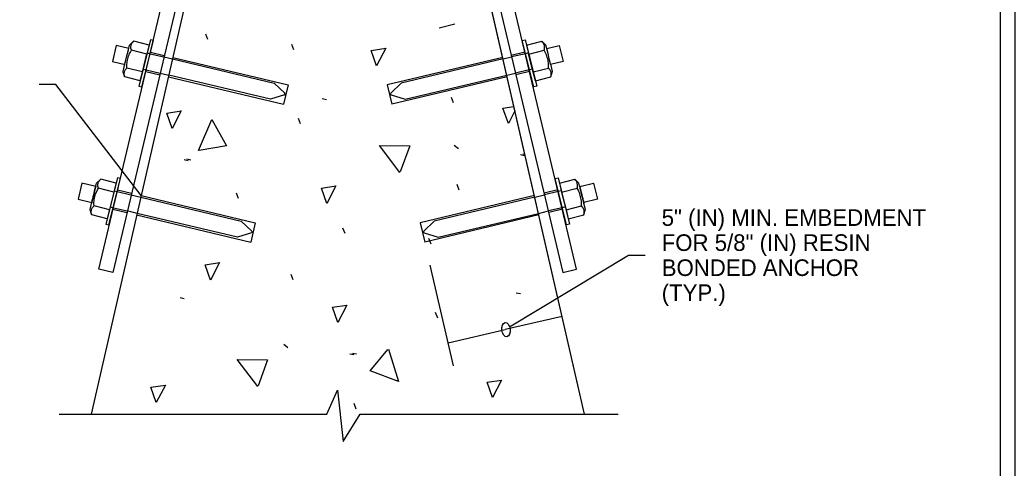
# Model space of a CAD drawing. Extents: x 99988 to 100172, y 99995 to 100047.
# Drawn here: x 100031.616 to 100035.812, y 100001.525 to 100003.415 of the extents above; entities that cross this region are included whole.
import ezdxf

# ---------------------------------------------------------------- set-up
doc = ezdxf.new("R2010")
doc.units = 0
for name, color, linetype in [('Level 10', 7, 'Continuous'), ('Level 12', 7, 'Continuous'), ('Level 15', 7, 'Continuous'), ('Level 18', 7, 'Continuous'), ('Level 20', 7, 'Continuous'), ('Level 8', 7, 'Continuous'), ('SH_GI_PlotLimits', 7, 'Continuous'), ('SH_GI_SheetBorder', 7, 'Continuous')]:
    doc.layers.add(name, color=color, linetype=linetype)

msp = doc.modelspace()

# ---------------------------------------------------------------- linework, layer by layer
at = {"layer": 'Level 10'}
for p, q in [((100033.3846, 100003.3813), (100033.4495, 100003.3976)), ((100032.0958, 100003.3251), (100032.0785, 100003.308)), ((100032.1609, 100003.3086), (100032.096, 100003.3248)), ((100032.1665, 100003.3309), (100032.1176, 100003.1356)), ((100032.1302, 100003.1324), (100032.1791, 100003.3277)), ((100032.1609, 100003.3086), (100032.1514, 100003.2708)), ((100032.1607, 100003.3088), (100032.1606, 100003.3086)), ((100032.1791, 100003.3277), (100032.1665, 100003.3309)), ((100033.7337, 100003.3277), (100033.7463, 100003.3309)), ((100033.7826, 100003.1324), (100033.7337, 100003.3277)), ((100033.7463, 100003.3309), (100033.7952, 100003.1356)), ((100033.7519, 100003.3086), (100033.8168, 100003.3248)), ((100033.7519, 100003.3086), (100033.7614, 100003.2708)), ((100033.817, 100003.3251), (100033.8343, 100003.308)), ((100032.1514, 100003.2708), (100032.0865, 100003.287)), ((100032.1324, 100003.1948), (100032.1515, 100003.2712)), ((100032.1514, 100003.2708), (100032.1327, 100003.1957)), ((100032.167, 100003.2792), (100032.2251, 100003.2654)), ((100032.2608, 100003.2569), (100032.7476, 100003.1411)), ((100033.6521, 100003.2569), (100033.1652, 100003.1411)), ((100033.7458, 100003.2792), (100033.6877, 100003.2654)), ((100033.7804, 100003.1948), (100033.7613, 100003.2712)), ((100033.7614, 100003.2708), (100033.8263, 100003.287)), ((100033.7614, 100003.2708), (100033.7802, 100003.1957)), ((100032.0509, 100003.1976), (100032.0572, 100003.2228)), ((100032.1327, 100003.1957), (100032.0677, 100003.212)), ((100033.7802, 100003.1957), (100033.8451, 100003.212)), ((100033.8619, 100003.1976), (100033.8556, 100003.2228)), ((100032.1232, 100003.1579), (100032.0582, 100003.1742)), ((100032.1327, 100003.1957), (100032.1232, 100003.1579)), ((100032.1232, 100003.1579), (100032.1324, 100003.1948)), ((100032.1476, 100003.1977), (100032.2058, 100003.1839)), ((100032.2421, 100003.1753), (100032.7282, 100003.0597)), ((100033.6707, 100003.1753), (100033.1846, 100003.0597)), ((100033.7652, 100003.1977), (100033.7071, 100003.1839)), ((100033.7802, 100003.1957), (100033.7896, 100003.1579)), ((100033.7896, 100003.1579), (100033.7804, 100003.1948)), ((100033.7896, 100003.1579), (100033.8546, 100003.1742)), ((100032.1176, 100003.1356), (100032.1302, 100003.1324)), ((100032.7476, 100003.1411), (100032.7282, 100003.0597)), ((100033.1652, 100003.1411), (100033.1846, 100003.0597)), ((100033.7952, 100003.1356), (100033.7826, 100003.1324)), ((100032.0275, 100002.7495), (100031.9786, 100002.5542)), ((100032.0401, 100002.7463), (100032.0275, 100002.7495)), ((100033.8727, 100002.7463), (100033.8853, 100002.7495)), ((100033.8853, 100002.7495), (100033.9342, 100002.5542)), ((100031.9369, 100002.7159), (100031.9395, 100002.7265)), ((100031.9568, 100002.7437), (100031.9395, 100002.7265)), ((100032.0125, 100002.6893), (100031.9475, 100002.7056)), ((100032.0219, 100002.7271), (100031.957, 100002.7434)), ((100031.9912, 100002.551), (100032.0401, 100002.7463)), ((100032.0219, 100002.7271), (100032.0125, 100002.6893)), ((100032.0217, 100002.7274), (100032.0217, 100002.7272)), ((100033.9216, 100002.551), (100033.8727, 100002.7463)), ((100033.8909, 100002.7271), (100033.9558, 100002.7434)), ((100033.8909, 100002.7271), (100033.9003, 100002.6893)), ((100033.8911, 100002.7274), (100033.8911, 100002.7272)), ((100033.9003, 100002.6893), (100033.9653, 100002.7056)), ((100033.956, 100002.7437), (100033.9733, 100002.7265)), ((100033.9759, 100002.7159), (100033.9733, 100002.7265)), ((100034.0346, 100002.7298), (100034.0346, 100002.7298)), ((100032.0125, 100002.6893), (100031.9937, 100002.6143)), ((100032.028, 100002.6978), (100032.0862, 100002.6839)), ((100032.1269, 100002.6742), (100032.6086, 100002.5597)), ((100033.7855, 100002.6741), (100033.3042, 100002.5597)), ((100033.8848, 100002.6978), (100033.8267, 100002.6839)), ((100033.9003, 100002.6893), (100033.9191, 100002.6143)), ((100031.9119, 100002.6162), (100031.9182, 100002.6413)), ((100031.9937, 100002.6143), (100031.9287, 100002.6306)), ((100033.9191, 100002.6143), (100033.9841, 100002.6306)), ((100034.0009, 100002.6162), (100033.9946, 100002.6413)), ((100031.9842, 100002.5765), (100031.9193, 100002.5927)), ((100031.9937, 100002.6143), (100031.9842, 100002.5765)), ((100032.0086, 100002.6163), (100032.0668, 100002.6025)), ((100032.108, 100002.5927), (100032.5893, 100002.4783)), ((100033.8042, 100002.5925), (100033.3235, 100002.4783)), ((100033.9042, 100002.6163), (100033.846, 100002.6025)), ((100033.9191, 100002.6143), (100033.9286, 100002.5765)), ((100033.9286, 100002.5765), (100033.9936, 100002.5927)), ((100031.9786, 100002.5542), (100031.9912, 100002.551)), ((100032.6086, 100002.5597), (100032.5893, 100002.4783)), ((100033.3042, 100002.5597), (100033.3235, 100002.4783)), ((100033.9342, 100002.5542), (100033.9216, 100002.551))]:
    msp.add_line(p, q, dxfattribs=at)
for points, degree in [([(100032.0572, 100003.2228), (100032.0572, 100003.2228), (100032.0653, 100003.2554), (100032.0785, 100003.308)], 3), ([(100032.0865, 100003.287), (100032.0843, 100003.2941), (100032.0835, 100003.301), (100032.0867, 100003.3139), (100032.0907, 100003.3196), (100032.096, 100003.3248)], 3), ([(100032.0865, 100003.287), (100032.0843, 100003.2941), (100032.0835, 100003.301), (100032.0867, 100003.3139), (100032.0907, 100003.3196), (100032.096, 100003.3248)], 3), ([(100033.8263, 100003.287), (100033.8285, 100003.2941), (100033.8293, 100003.301), (100033.8261, 100003.3139), (100033.8221, 100003.3196), (100033.8168, 100003.3248)], 3), ([(100033.8263, 100003.287), (100033.8285, 100003.2941), (100033.8293, 100003.301), (100033.8261, 100003.3139), (100033.8221, 100003.3196), (100033.8168, 100003.3248)], 3), ([(100033.8556, 100003.2228), (100033.8556, 100003.2228), (100033.8476, 100003.2554), (100033.8343, 100003.308)], 3), ([(100032.0677, 100003.212), (100032.0671, 100003.2252), (100032.0678, 100003.2382), (100032.0742, 100003.2637), (100032.0797, 100003.2757), (100032.0865, 100003.287)], 3), ([(100032.0688, 100003.2691), (100032.0688, 100003.269), (100032.0687, 100003.2689), (100032.0687, 100003.2689)], 3), ([(100033.8451, 100003.212), (100033.8458, 100003.2252), (100033.845, 100003.2382), (100033.8386, 100003.2637), (100033.8331, 100003.2757), (100033.8263, 100003.287)], 3), ([(100033.844, 100003.2691), (100033.844, 100003.269), (100033.8441, 100003.2689), (100033.8441, 100003.2689)], 3), ([(100032.0582, 100003.1742), (100032.056, 100003.1813), (100032.0552, 100003.1881), (100032.0584, 100003.201), (100032.0624, 100003.2068), (100032.0677, 100003.212)], 3), ([(100032.0582, 100003.1742), (100032.056, 100003.1813), (100032.0552, 100003.1881), (100032.0584, 100003.201), (100032.0624, 100003.2068), (100032.0677, 100003.212)], 3), ([(100033.8546, 100003.1742), (100033.8568, 100003.1813), (100033.8576, 100003.1881), (100033.8544, 100003.201), (100033.8504, 100003.2068), (100033.8451, 100003.212)], 3), ([(100033.8546, 100003.1742), (100033.8568, 100003.1813), (100033.8576, 100003.1881), (100033.8544, 100003.201), (100033.8504, 100003.2068), (100033.8451, 100003.212)], 3), ([(100032.0579, 100003.1747), (100032.0556, 100003.1824), (100032.0532, 100003.19), (100032.0509, 100003.1976)], 2), ([(100033.8549, 100003.1747), (100033.8572, 100003.1824), (100033.8596, 100003.19), (100033.8619, 100003.1976)], 2), ([(100031.9182, 100002.6413), (100031.9182, 100002.6413), (100031.9369, 100002.7159), (100031.9369, 100002.7159), (100031.9369, 100002.7159), (100031.9182, 100002.6413), (100031.9182, 100002.6413)], 4), ([(100031.9287, 100002.6306), (100031.9281, 100002.6437), (100031.9289, 100002.6567), (100031.9352, 100002.6823), (100031.9408, 100002.6943), (100031.9475, 100002.7056)], 3), ([(100031.9475, 100002.7056), (100031.9453, 100002.7127), (100031.9445, 100002.7195), (100031.9477, 100002.7324), (100031.9517, 100002.7382), (100031.957, 100002.7434)], 3), ([(100031.9475, 100002.7056), (100031.9453, 100002.7127), (100031.9445, 100002.7195), (100031.9477, 100002.7324), (100031.9517, 100002.7382), (100031.957, 100002.7434)], 3), ([(100033.9653, 100002.7056), (100033.9675, 100002.7127), (100033.9683, 100002.7195), (100033.9651, 100002.7324), (100033.9611, 100002.7382), (100033.9558, 100002.7434)], 3), ([(100033.9653, 100002.7056), (100033.9675, 100002.7127), (100033.9683, 100002.7195), (100033.9651, 100002.7324), (100033.9611, 100002.7382), (100033.9558, 100002.7434)], 3), ([(100033.9841, 100002.6306), (100033.9847, 100002.6437), (100033.984, 100002.6567), (100033.9776, 100002.6823), (100033.9721, 100002.6943), (100033.9653, 100002.7056)], 3), ([(100033.9946, 100002.6413), (100033.9946, 100002.6413), (100033.9759, 100002.7159), (100033.9759, 100002.7159), (100033.9759, 100002.7159), (100033.9946, 100002.6413), (100033.9946, 100002.6413)], 4), ([(100031.9193, 100002.5927), (100031.9171, 100002.5998), (100031.9162, 100002.6067), (100031.9194, 100002.6196), (100031.9234, 100002.6253), (100031.9287, 100002.6306)], 3), ([(100031.9193, 100002.5927), (100031.9171, 100002.5998), (100031.9162, 100002.6067), (100031.9194, 100002.6196), (100031.9234, 100002.6253), (100031.9287, 100002.6306)], 3), ([(100033.9936, 100002.5927), (100033.9957, 100002.5998), (100033.9966, 100002.6067), (100033.9934, 100002.6196), (100033.9894, 100002.6253), (100033.9841, 100002.6306)], 3), ([(100033.9936, 100002.5927), (100033.9957, 100002.5998), (100033.9966, 100002.6067), (100033.9934, 100002.6196), (100033.9894, 100002.6253), (100033.9841, 100002.6306)], 3), ([(100031.919, 100002.5933), (100031.9166, 100002.6009), (100031.9143, 100002.6086), (100031.9119, 100002.6162)], 2), ([(100033.9939, 100002.5933), (100033.9962, 100002.6009), (100033.9985, 100002.6086), (100034.0009, 100002.6162)], 2)]:
    msp.add_open_spline(points, degree=degree, dxfattribs=at)
at = {"layer": 'Level 12'}
for points in [[(100032.5051, 100004.4431), (100032.0075, 100002.35), (100031.9493, 100002.3638), (100032.447, 100004.4569)], [(100033.4073, 100004.4431), (100033.9049, 100002.35), (100033.9631, 100002.3638), (100033.4655, 100004.4569)]]:
    msp.add_lwpolyline(points, close=True, dxfattribs=at)
at = {"layer": 'Level 15'}
for p, q in [((100033.4438, 100001.9566), (100033.3467, 100002.381)), ((100033.9023, 100002.1641), (100033.6619, 100002.1091)), ((100033.4215, 100002.054), (100033.6619, 100002.1091)), ((100031.7814, 100001.7525), (100032.9098, 100001.7525)), ((100033.0512, 100001.7525), (100034.1381, 100001.7525))]:
    msp.add_line(p, q, dxfattribs=at)
for points in [[(100032.1269, 100002.6742), (100031.768, 100003.1424), (100031.698, 100003.1424)], [(100033.6808, 100002.1205), (100034.1823, 100002.4231), (100034.2523, 100002.4231)], [(100032.9098, 100001.7525), (100032.9559, 100001.8537), (100032.9792, 100001.6376), (100033.0512, 100001.7525)]]:
    msp.add_lwpolyline(points, dxfattribs=at)
msp.add_ellipse((100033.6658, 100002.1091), major_axis=(-0.0041, 0.0297), ratio=0.57735, dxfattribs=at)
at = {"layer": 'Level 18'}
for p, q in [((100032.0226, 100003.3068), (100032.0065, 100003.2389)), ((100032.0754, 100003.2942), (100032.0226, 100003.3068)), ((100033.8374, 100003.2942), (100033.8902, 100003.3068)), ((100033.8902, 100003.3068), (100033.9063, 100003.2389)), ((100032.1526, 100003.2754), (100032.1653, 100003.2724)), ((100032.1653, 100003.2724), (100032.2235, 100003.2586)), ((100032.2235, 100003.2586), (100032.2592, 100003.2501)), ((100033.6536, 100003.2501), (100033.6893, 100003.2586)), ((100033.7475, 100003.2724), (100033.6893, 100003.2586)), ((100033.7602, 100003.2754), (100033.7475, 100003.2724)), ((100032.0065, 100003.2389), (100032.0595, 100003.2263)), ((100032.2592, 100003.2501), (100032.6887, 100003.148)), ((100033.6536, 100003.2501), (100033.2241, 100003.148)), ((100033.9063, 100003.2389), (100033.8533, 100003.2263)), ((100032.1356, 100003.2078), (100032.1492, 100003.2045)), ((100032.1492, 100003.2045), (100032.2074, 100003.1907)), ((100032.2074, 100003.1907), (100032.2436, 100003.1821)), ((100032.6726, 100003.0801), (100032.2436, 100003.1821)), ((100033.2402, 100003.0801), (100033.6692, 100003.1821)), ((100033.6692, 100003.1821), (100033.7054, 100003.1907)), ((100033.7636, 100003.2045), (100033.7054, 100003.1907)), ((100033.7772, 100003.2078), (100033.7636, 100003.2045)), ((100032.6887, 100003.148), (100032.7328, 100003.1053)), ((100033.2241, 100003.148), (100033.18, 100003.1053)), ((100032.7312, 100003.0983), (100032.6726, 100003.0801)), ((100033.1816, 100003.0983), (100033.2402, 100003.0801)), ((100031.8774, 100002.7264), (100031.8613, 100002.6585)), ((100031.936, 100002.7125), (100031.8774, 100002.7264)), ((100033.9768, 100002.7125), (100034.0354, 100002.7264)), ((100034.0354, 100002.7264), (100034.0515, 100002.6585)), ((100032.0138, 100002.694), (100032.0264, 100002.691)), ((100032.0264, 100002.691), (100032.0845, 100002.6771)), ((100032.0845, 100002.6771), (100032.1258, 100002.6673)), ((100032.1258, 100002.6673), (100032.5498, 100002.5665)), ((100033.787, 100002.6673), (100033.363, 100002.5665)), ((100033.787, 100002.6673), (100033.8283, 100002.6771)), ((100033.8864, 100002.691), (100033.8283, 100002.6771)), ((100033.899, 100002.694), (100033.8864, 100002.691)), ((100031.8613, 100002.6585), (100031.9191, 100002.6448)), ((100031.9964, 100002.6264), (100032.0103, 100002.6231)), ((100032.0103, 100002.6231), (100032.0684, 100002.6093)), ((100033.9026, 100002.6231), (100033.8444, 100002.6093)), ((100033.9164, 100002.6264), (100033.9026, 100002.6231)), ((100034.0515, 100002.6585), (100033.9937, 100002.6448)), ((100032.1102, 100002.5993), (100032.0684, 100002.6093)), ((100032.5336, 100002.4987), (100032.1102, 100002.5993)), ((100033.3792, 100002.4987), (100033.8026, 100002.5993)), ((100033.8026, 100002.5993), (100033.8444, 100002.6093)), ((100032.5498, 100002.5665), (100032.5939, 100002.5239)), ((100033.363, 100002.5665), (100033.3189, 100002.5239)), ((100032.5922, 100002.5169), (100032.5336, 100002.4987)), ((100033.3206, 100002.5169), (100033.3792, 100002.4987))]:
    msp.add_line(p, q, dxfattribs=at)
for centre, start, end in [((100032.7299, 100003.1023), 287.2722, 45.9747), ((100033.1829, 100003.1023), 134.0253, 252.7278), ((100032.591, 100002.5209), 287.2722, 45.9747), ((100033.3218, 100002.5209), 134.0253, 252.7278)]:
    msp.add_arc(centre, 0.00419, start, end, dxfattribs=at)
at = {"layer": 'Level 8'}
for p, q in [((100032.4973, 100004.2901), (100031.9163, 100001.7525)), ((100033.9965, 100001.7525), (100033.4155, 100004.2901)), ((100032.4087, 100003.3323), (100032.3999, 100003.3551)), ((100032.7714, 100003.2885), (100032.7626, 100003.3113)), ((100032.8907, 100003.0833), (100032.9083, 100003.0798)), ((100033.4445, 100003.0646), (100033.4357, 100003.0874)), ((100032.7996, 100002.9764), (100032.7909, 100002.9992)), ((100033.4476, 100002.8865), (100033.4652, 100002.8724)), ((100033.7264, 100002.8468), (100033.744, 100002.8433)), ((100033.7374, 100002.8498), (100033.7456, 100002.8482)), ((100032.3088, 100002.826), (100032.3263, 100002.8225)), ((100032.3198, 100002.829), (100032.3374, 100002.8255)), ((100033.4682, 100002.6976), (100033.4594, 100002.7203)), ((100032.5382, 100002.6613), (100032.5294, 100002.6841)), ((100032.9871, 100002.5139), (100032.9783, 100002.5367)), ((100033.3498, 100002.4701), (100033.341, 100002.4929)), ((100032.769, 100002.3195), (100032.7602, 100002.3422)), ((100032.2915, 100002.2441), (100032.309, 100002.2406)), ((100033.7091, 100002.2649), (100033.7267, 100002.2614)), ((100033.378, 100002.1581), (100033.3692, 100002.1808)), ((100032.7284, 100002.0472), (100032.7459, 100002.0332)), ((100033.0072, 100002.0076), (100033.0247, 100002.0041)), ((100033.0182, 100002.0106), (100033.0357, 100002.0071)), ((100033.0337, 100001.7743), (100033.0249, 100001.7971))]:
    msp.add_line(p, q, dxfattribs=at)
for points in [[(100033.9965, 100001.7525), (100033.4155, 100004.2901), (100033.3616, 100004.3376), (100033.3146, 100004.379), (100032.5982, 100004.379), (100032.4973, 100004.2901)], [(100033.1203, 100003.2217), (100033.0975, 100003.2865), (100033.1588, 100003.2953), (100033.1203, 100003.2217)], [(100033.6757, 100002.9782), (100033.6529, 100003.0431), (100033.6995, 100003.0497)], [(100032.258, 100002.9574), (100032.2353, 100003.0222), (100032.2966, 100003.031), (100032.258, 100002.9574)], [(100033.7036, 100003.0316), (100033.6757, 100002.9782)], [(100032.3697, 100002.8637), (100032.4252, 100002.9954), (100032.4873, 100002.884), (100032.3722, 100002.8639)], [(100033.2184, 100002.7719), (100033.1321, 100002.8859), (100033.2597, 100002.8838), (100033.2194, 100002.7741)], [(100032.9103, 100002.6413), (100032.8875, 100002.7061), (100032.9489, 100002.7149), (100032.9103, 100002.6413)], [(100032.4199, 100002.3181), (100032.3971, 100002.383), (100032.4584, 100002.3917), (100032.4199, 100002.3181)], [(100032.9564, 100002.139), (100032.9337, 100002.2038), (100032.995, 100002.2126), (100032.9564, 100002.139)], [(100033.1698, 100002.027), (100033.2119, 100001.8903), (100033.0927, 100001.9359), (100033.1681, 100002.0252)], [(100032.6191, 100001.8697), (100032.5329, 100001.9837), (100032.6604, 100001.9817), (100032.6202, 100001.872)], [(100032.1911, 100001.8021), (100032.1683, 100001.8669), (100032.2296, 100001.8757), (100032.1911, 100001.8021)], [(100033.6087, 100001.8229), (100033.5859, 100001.8877), (100033.6472, 100001.8965), (100033.6087, 100001.8229)]]:
    msp.add_lwpolyline(points, dxfattribs=at)
at = {"layer": 'SH_GI_PlotLimits'}
msp.add_lwpolyline([(100019.3125, 99999.9375), (100035.8125, 99999.9375), (100035.8125, 100010.4375), (100019.3125, 100010.4375)], close=True, dxfattribs=at)
at = {"layer": 'SH_GI_SheetBorder'}
msp.add_line((100035.75, 100010.375), (100035.75, 100000), dxfattribs=at)

# ---------------------------------------------------------------- texts
at = {"layer": 'Level 20'}
for s, p in [('5" (IN) MIN. EMBEDMENT', (100034.3223, 100002.5465)), ('FOR 5/8" (IN) RESIN', (100034.3223, 100002.4409)), ('BONDED ANCHOR', (100034.3223, 100002.3353)), ('(TYP.)', (100034.3223, 100002.2298))]:
    msp.add_text(s, height=0.07, rotation=360, dxfattribs=at).set_placement(p)

doc.saveas('drawing.dxf')
